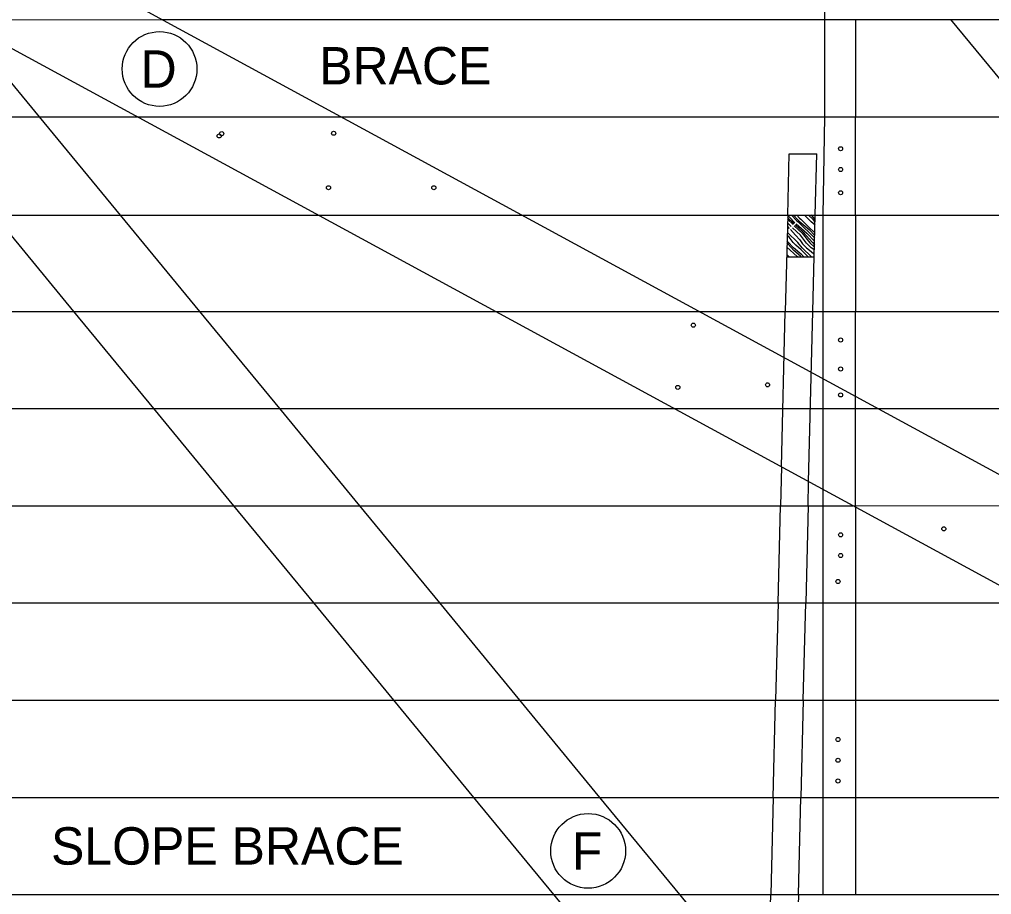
# Model space of a CAD drawing. Extents: x 49991 to 79985, y 47703 to 60542.
# Drawn here: x 50002.281 to 50003.842, y 49995.596 to 49997.001 of the extents above; entities that cross this region are included whole.
import ezdxf

# ---------------------------------------------------------------- set-up
doc = ezdxf.new("R2010")
doc.units = 0
for name, color, linetype in [('Level 1', 7, 'Continuous'), ('Level 2', 7, 'Continuous'), ('Level 4', 7, 'Continuous')]:
    doc.layers.add(name, color=color, linetype=linetype)

msp = doc.modelspace()

# ---------------------------------------------------------------- linework, layer by layer
at = {"layer": 'Level 1'}
for p, q in [((50005.8334, 49995.1946), (50001.4473, 49997.5783)), ((50005.759, 49995.0576), (50001.3728, 49997.4412)), ((50002.1851, 49996.9997), (50002.3131, 49996.8443)), ((50002.5099, 49997.0008), (50006.0719, 49997.0008)), ((50003.5742, 49996.8443), (50003.5742, 49997.0008)), ((50003.6236, 49997.0008), (50003.6236, 49996.8443)), ((50003.7762, 49997.0008), (50003.9051, 49996.8443)), ((50001.0799, 49996.8443), (50002.4712, 49996.8443)), ((50002.7979, 49996.8443), (50006.0719, 49996.8443)), ((50001.0799, 49996.6868), (50002.7611, 49996.6868)), ((50002.2409, 49996.6868), (50002.3681, 49996.5323)), ((50002.4429, 49996.6868), (50002.5702, 49996.5323)), ((50003.0878, 49996.6868), (50006.0719, 49996.6868)), ((50003.5147, 49996.6868), (50003.5109, 49996.5323)), ((50003.5552, 49996.5323), (50003.5591, 49996.6868)), ((50003.5716, 49996.5323), (50003.5716, 49996.6868)), ((50003.6236, 49996.6868), (50003.6236, 49996.5323)), ((50003.5295, 49996.6776), (50003.5314, 49996.6758)), ((50003.5311, 49996.6792), (50003.5329, 49996.6773)), ((50003.5339, 49996.682), (50003.5358, 49996.6802)), ((50003.513, 49996.6196), (50003.5574, 49996.6196)), ((50001.0799, 49996.5323), (50003.0453, 49996.5323)), ((50003.372, 49996.5323), (50006.0719, 49996.5323)), ((50001.0799, 49996.3763), (50003.3324, 49996.3763)), ((50002.4966, 49996.3763), (50002.6251, 49996.2203)), ((50002.6987, 49996.3763), (50002.8272, 49996.2203)), ((50003.6591, 49996.3763), (50006.0719, 49996.3763)), ((50003.5046, 49996.2827), (50003.5031, 49996.2203)), ((50003.5474, 49996.2203), (50003.5484, 49996.2589)), ((50003.5716, 49996.2203), (50003.5716, 49996.2463)), ((50001.0799, 49996.2203), (50003.6194, 49996.2203)), ((50001.0799, 49996.0643), (50003.9065, 49996.0643)), ((50002.7536, 49996.0643), (50002.882, 49995.9083)), ((50002.9557, 49996.0643), (50003.0841, 49995.9083)), ((50003.4992, 49996.0643), (50003.4953, 49995.9083)), ((50003.5397, 49995.9083), (50003.5436, 49996.0643)), ((50003.5716, 49995.9083), (50003.5716, 49996.0643)), ((50003.6236, 49996.0643), (50003.6236, 49995.9083)), ((50001.0799, 49995.9083), (50004.1936, 49995.9083)), ((50001.0799, 49995.7523), (50004.4806, 49995.7523)), ((50003.0105, 49995.7523), (50003.139, 49995.5963)), ((50003.2126, 49995.7523), (50003.3411, 49995.5963)), ((50003.4915, 49995.7523), (50003.4876, 49995.5963)), ((50003.5319, 49995.5963), (50003.5358, 49995.7523)), ((50003.5716, 49995.5963), (50003.5716, 49995.7523)), ((50003.6236, 49995.7523), (50003.6236, 49995.5963)), ((50001.0799, 49995.5963), (50004.7677, 49995.5963))]:
    msp.add_line(p, q, dxfattribs=at)
for points in [[(50003.5147, 49996.6864), (50003.5175, 49996.6835), (50003.5264, 49996.6745)], [(50003.5206, 49996.6868), (50003.5295, 49996.6776)], [(50003.5243, 49996.6868), (50003.5311, 49996.6792)], [(50003.5292, 49996.6868), (50003.5339, 49996.682)], [(50003.5586, 49996.6705), (50003.5525, 49996.6761), (50003.5418, 49996.6868)], [(50003.5588, 49996.6762), (50003.5555, 49996.6798), (50003.5482, 49996.6868)], [(50003.5589, 49996.6798), (50003.5551, 49996.684), (50003.5518, 49996.6868)], [(50003.5203, 49996.6684), (50003.5144, 49996.6746)], [(50003.5145, 49996.6803), (50003.5234, 49996.6715)], [(50003.5146, 49996.6831), (50003.5249, 49996.673)], [(50003.5253, 49996.6697), (50003.5382, 49996.6577), (50003.5502, 49996.6421), (50003.5578, 49996.6355)], [(50003.5267, 49996.6712), (50003.5396, 49996.6592), (50003.5543, 49996.643), (50003.5579, 49996.6393)], [(50003.5283, 49996.6727), (50003.5367, 49996.6652), (50003.5453, 49996.6576), (50003.558, 49996.6449)], [(50003.5314, 49996.6758), (50003.5581, 49996.65)], [(50003.5329, 49996.6773), (50003.5398, 49996.6718), (50003.5491, 49996.6635), (50003.5582, 49996.6542)], [(50003.5358, 49996.6802), (50003.5484, 49996.668), (50003.5583, 49996.6582)], [(50003.5474, 49996.6196), (50003.5366, 49996.6312), (50003.5278, 49996.6383), (50003.5236, 49996.6428), (50003.5171, 49996.6512), (50003.5139, 49996.6539)], [(50003.5142, 49996.6683), (50003.5172, 49996.6653)], [(50003.5529, 49996.6196), (50003.5382, 49996.6345), (50003.5311, 49996.643), (50003.5145, 49996.6589)], [(50003.5191, 49996.6635), (50003.5273, 49996.6548), (50003.5341, 49996.6471), (50003.5386, 49996.6408), (50003.545, 49996.6341), (50003.5499, 49996.6304), (50003.5563, 49996.6253), (50003.5575, 49996.6242)], [(50003.5576, 49996.6307), (50003.5567, 49996.6314), (50003.5523, 49996.634), (50003.5447, 49996.6416), (50003.5351, 49996.6546), (50003.5222, 49996.6666)], [(50003.5363, 49996.6196), (50003.5355, 49996.6207), (50003.5246, 49996.6299), (50003.5156, 49996.64), (50003.5136, 49996.6419)], [(50003.5407, 49996.6196), (50003.5375, 49996.6231), (50003.5239, 49996.6344), (50003.5152, 49996.6441), (50003.5137, 49996.6454)], [(50003.5171, 49996.6196), (50003.5131, 49996.6235)], [(50003.5308, 49996.6196), (50003.53, 49996.6205), (50003.5134, 49996.6355)], [(50003.5131, 49996.6196), (50003.513, 49996.6198)]]:
    msp.add_lwpolyline(points, dxfattribs=at)
for centre in [(50002.602, 49996.8139), (50002.6061, 49996.8175), (50002.7858, 49996.8181), (50003.5997, 49996.7933), (50003.5997, 49996.76), (50002.7775, 49996.7307), (50002.9467, 49996.7307), (50003.5997, 49996.7226), (50003.3633, 49996.5101), (50003.5997, 49996.4863), (50003.5997, 49996.4398), (50003.3383, 49996.4102), (50003.4824, 49996.4144), (50003.5997, 49996.3982), (50003.7654, 49996.1833), (50003.5997, 49996.1736), (50003.5997, 49996.1404), (50003.5955, 49996.0988), (50003.5955, 49995.8451), (50003.5955, 49995.8118), (50003.5955, 49995.7786)]:
    msp.add_circle(centre, 0.00327, dxfattribs=at)
at = {"layer": 'Level 2'}
for centre in [(50002.5063, 49996.9213), (50003.1944, 49995.6664)]:
    msp.add_circle(centre, 0.06, dxfattribs=at)
at = {"layer": 'Level 4'}
for p, q in [((50003.5742, 49997.0008), (50003.5742, 49997.1563)), ((50002.1841, 49997.0003), (50002.5099, 49997.0008)), ((50002.3131, 49996.8443), (50002.4429, 49996.6868)), ((50002.4712, 49996.8443), (50002.7979, 49996.8443)), ((50003.5716, 49996.6868), (50003.5742, 49996.8443)), ((50003.6236, 49996.6868), (50003.6236, 49996.8443)), ((50003.5147, 49996.6868), (50003.5171, 49996.785)), ((50003.5171, 49996.785), (50003.5615, 49996.785)), ((50003.5591, 49996.6868), (50003.5615, 49996.785)), ((50002.7611, 49996.6868), (50003.0878, 49996.6868)), ((50002.3681, 49996.5323), (50002.4966, 49996.3763)), ((50002.5702, 49996.5323), (50002.6987, 49996.3763)), ((50003.0453, 49996.5323), (50003.372, 49996.5323)), ((50003.5046, 49996.2827), (50003.5109, 49996.5323)), ((50003.5484, 49996.2589), (50003.5552, 49996.5323)), ((50003.5716, 49996.2463), (50003.5716, 49996.5323)), ((50003.6236, 49996.2198), (50003.6236, 49996.5323)), ((50003.3324, 49996.3763), (50003.6591, 49996.3763)), ((50002.6251, 49996.2203), (50002.7536, 49996.0643)), ((50002.8272, 49996.2203), (50002.9557, 49996.0643)), ((50003.4992, 49996.0643), (50003.5031, 49996.2203)), ((50003.5474, 49996.2203), (50003.5436, 49996.0643)), ((50003.5716, 49996.0643), (50003.5716, 49996.2203)), ((50003.6194, 49996.2203), (50003.9452, 49996.2208)), ((50003.6236, 49996.2198), (50003.6236, 49996.0643)), ((50002.882, 49995.9083), (50003.0105, 49995.7523)), ((50003.0841, 49995.9083), (50003.2126, 49995.7523)), ((50003.4915, 49995.7523), (50003.4953, 49995.9083)), ((50003.5397, 49995.9083), (50003.5358, 49995.7523)), ((50003.5716, 49995.7523), (50003.5716, 49995.9083)), ((50003.6236, 49995.9083), (50003.6236, 49995.7523)), ((50003.139, 49995.5963), (50003.2675, 49995.4403)), ((50003.3411, 49995.5963), (50003.4696, 49995.4403)), ((50003.4759, 49995.1283), (50003.4876, 49995.5963)), ((50003.5319, 49995.5963), (50003.5281, 49995.4403))]:
    msp.add_line(p, q, dxfattribs=at)

# ---------------------------------------------------------------- texts
at = {"layer": 'Level 2'}
for s, p in [('D', (50002.4759, 49996.8913)), ('BRACE', (50002.7626, 49996.8965)), ('SLOPE BRACE', (50002.3321, 49995.6443)), ('F', (50003.1682, 49995.6364))]:
    msp.add_text(s, height=0.06, dxfattribs=at).set_placement(p)

doc.saveas('drawing.dxf')
